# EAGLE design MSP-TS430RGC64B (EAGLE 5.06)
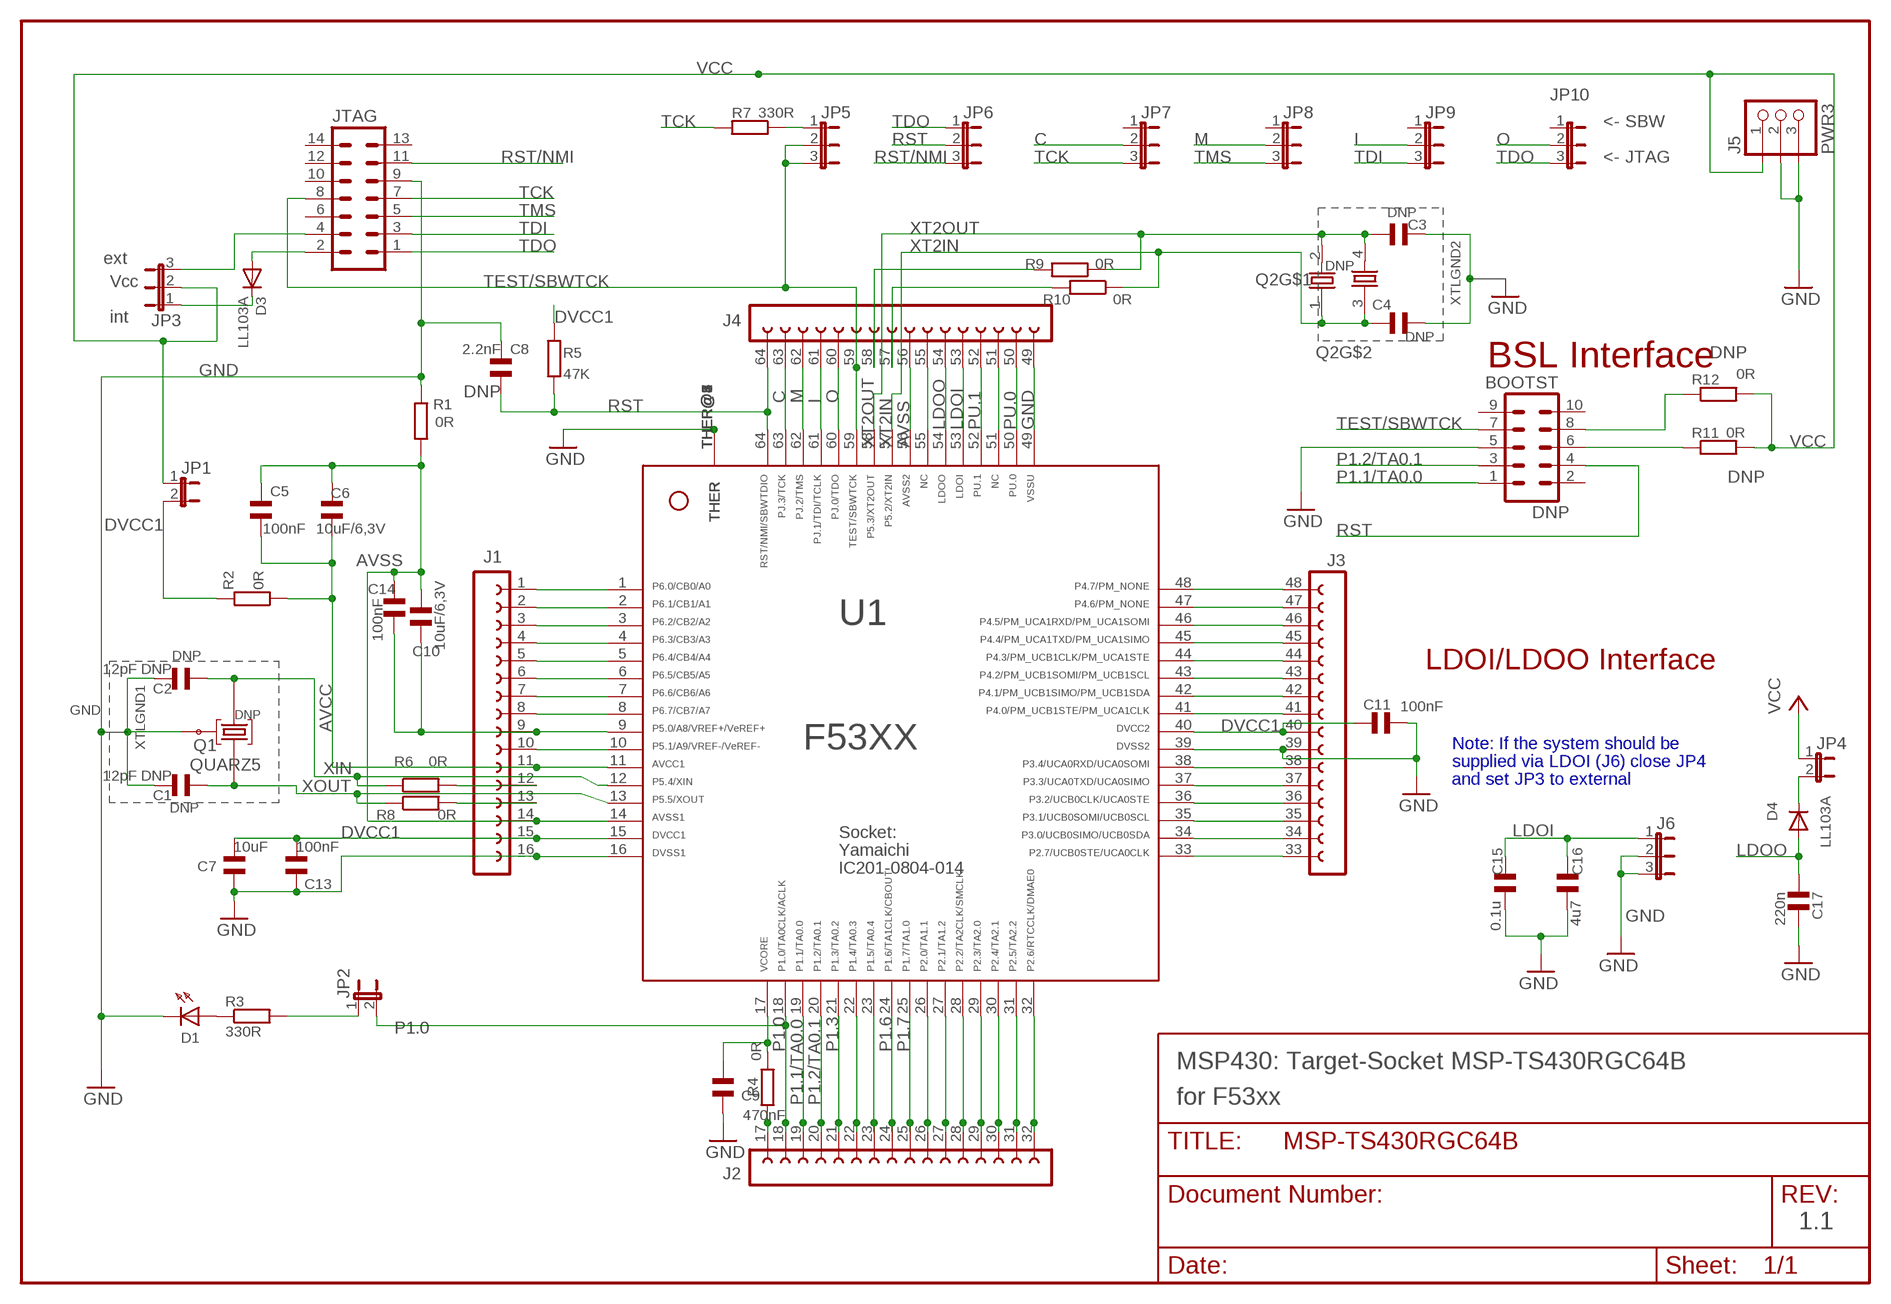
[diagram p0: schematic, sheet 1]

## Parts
BOOTST  ML10  [ML10]
C1  12pF DNP  CSMD0805  [CSMD0805]
C2  12pF DNP  CSMD0805  [CSMD0805]
C3  47pF  CSMD0805  [CSMD0805]
C4  47pF  CSMD0805  [CSMD0805]
C5  100nF  CSMD0805  [CSMD0805]
C6  10uF/6,3V  CSMD0805  [CSMD0805]
C7  10uF  CSMD0805  [CSMD0805]
C8  2.2nF  CSMD0805  [CSMD0805]
C9  470nF  CSMD0805  [CSMD0805]
C10  10uF/6,3V  CSMD0805  [CSMD0805]
C11  100nF  CSMD0805  [CSMD0805]
C13  100nF  CSMD0805  [CSMD0805]
C14  100nF  CSMD0805  [CSMD0805]
C15  0.1u  C_SMD0805  [0805]
C16  4u7  C_SMD0805  [0805]
C17  220n  C_SMD0805  [0805]
D1  LED30805  [DIODE_0805]
D3  LL103A  D  [SOD-80]
D4  LL103A  D  [SOD-80]
J1  FE16-1-1  [FE16-1-1]
J2  FE16-1-2  [FE16-1-2]
J3  FE16-1-3  [FE16-1-3]
J4  FE16-1-4  [FE16-1-4]
J5  PWR3  [PWR3]
J6  JP2ESMALLPAD  [JP2Z]
JP1  JP1E  [JP1]
JP2  JP1E  [JP1]
JP3  JP2ESMALLPAD  [JP2Z]
JP4  JP1E  [JP1]
JP5  JP2ESMALLPAD  [JP2Z]
JP6  JP2ESMALLPAD  [JP2Z]
JP7  JP2ESMALLPAD  [JP2Z]
JP8  JP2ESMALLPAD  [JP2Z]
JP9  JP2ESMALLPAD  [JP2Z]
JP10  JP2ESMALLPAD  [JP2Z]
JTAG  ML14  [ML14]
Q1  QUARZ5  [QUARZ5]
Q2  HCTC_XTL_4  [HCTC]
R1  0R  R_0805  [0805]
R2  0R  R_0805  [0805]
R3  330R  R_0805  [0805]
R4  0R  R_0805  [0805]
R5  47K  R_0805  [0805]
R6  0R  R_0805  [0805]
R7  330R  R_0805  [0805]
R8  0R  R_0805  [0805]
R9  0R  R_0805  [0805]
R10  0R  R_0805  [0805]
R11  0R  R_0805  [0805]
R12  0R  R_0805  [0805]
U1  F53XX---RGC64--S-PQFP-N64  [YAMAICHI-QFN11T064-006]

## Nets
51 [small]: J4.51 U1.51
56 [small]: J4.55 U1.55
AVCC [small]: C5.1 C6.2 J1.11 R2.1 U1.11
AVSS [small]: C5.2 C6.1 C10.2 C14.2 J1.14 J4.56 R1.2 U1.14 U1.56
C: J4.63 JP7.2 U1.63
DVCC1: C7.2 C11.1 C13.2 J1.15 J3.40 JP1.2 R2.2 R5.2 U1.15 U1.40
GND [small]: BOOTST.5 C7.1 C8.1 C9.1 C11.2 C13.1 C15.2 C16.2 C17.2 D1.K J1.16 J3.39 J4.49 J5.2 J5.3 J6.2 J6.3 JTAG.9 R1.1 U1.16 U1.39 U1.49 U1.THER@1(THER) U1.THER@2(THER) U1.THER@3(THER) U1.THER@4(THER) U1.THER@5(THER) U1.THER@6(THER) U1.THER@7(THER) U1.THER@8(THER)
I [small]: J4.61 JP9.2 U1.61
LDOI [small]: C15.1 C16.1 J4.53 J6.1 U1.53
LDOO [small]: C17.1 D4.1(A) J4.54 U1.54
M [small]: J4.62 JP8.2 U1.62
N$1: JP2.1 R3.2
N$3 [small]: C10.1 C14.1 J1.9 U1.9
N$4 [small]: J2.17 R4.1
N$5: J4.58 R9.2
N$6: J1.12 R6.2
N$7: D3.2(K) JP3.1
N$8: BOOTST.8 R12.1
N$9: J1.1 U1.1
N$10: J1.13 R8.2
N$11: J4.57 R10.2
N$12: J1.2 U1.2
N$13: J1.3 U1.3
N$14 [small]: J2.26 U1.26
N$15 [small]: J1.4 U1.4
N$16: BOOTST.6 R11.1
N$17 [small]: J2.23 U1.23
N$18: D1.A R3.1
N$19 [small]: J1.6 U1.6
N$20 [small]: J2.27 U1.27
N$21: J2.31 U1.31
N$22 [small]: J1.10 U1.10
N$23: JP3.3 JTAG.4
N$25: J3.33 U1.33
N$26 [small]: C9.2 R4.2 U1.17
N$27 [small]: J3.34 U1.34
N$28 [small]: J1.7 U1.7
N$29: J3.35 U1.35
N$30: D4.2(K) JP4.2
N$33 [small]: J3.36 U1.36
N$34: J2.28 U1.28
N$38: D3.1(A) JTAG.2
N$39 [small]: J3.37 U1.37
N$40: J3.38 U1.38
N$41: J3.41 U1.41
N$42 [small]: J3.42 U1.42
N$46: J2.22 U1.22
N$47 [small]: J3.43 U1.43
N$48: J3.44 U1.44
N$49 [small]: J3.45 U1.45
N$50 [small]: J3.46 U1.46
N$52: J3.47 U1.47
N$53: J3.48 U1.48
N$55 [small]: J2.29 U1.29
N$56 [small]: J2.30 U1.30
N$57: JP5.1 R7.1
N$58: J2.32 U1.32
N$99 [small]: J1.8 U1.8
N$102 [small]: J1.5 U1.5
O [small]: J4.60 JP10.2 U1.60
P1.0: J2.18 JP2.2 U1.18
P1.1/TA0.0: BOOTST.1 J2.19 U1.19
P1.2/TA0.1: BOOTST.3 J2.20 U1.20
P1.3 [small]: J2.21 U1.21
P1.6 [small]: J2.24 U1.24
P1.7: J2.25 U1.25
PU.0 [small]: J4.50 U1.50
PU.1 [small]: J4.52 U1.52
RST [small]: BOOTST.4 C8.2 J4.64 JP6.2 R5.1 U1.64
RST/NMI: JP6.3 JTAG.11
TCK: JP7.3 JTAG.7 R7.2
TDI: JP9.3 JTAG.3
TDO: JP6.1 JP10.3 JTAG.1
TEST/SBWTCK: BOOTST.7 J4.59 JP5.2 JP5.3 JTAG.8 U1.59
TMS: JP8.3 JTAG.5
VCC: J5.1 JP1.1 JP3.2 JP4.1 R11.2 R12.2
XIN: C2.1 Q1.1 R6.1 U1.12
XOUT [small]: C1.1 Q1.2 R8.1 U1.13
XT2IN [small]: C4.1 Q2.1 Q2.3 R10.1 U1.57
XT2OUT [small]: C3.1 Q2.2 Q2.4 R9.1 U1.58
XTLGND1: C1.2 C2.2 Q1.GND@0
XTLGND2: C3.2 C4.2
Unconnected: BOOTST.2 BOOTST.9 BOOTST.10 JP7.1 JP8.1 JP9.1 JP10.1 JTAG.6 JTAG.10 JTAG.12 JTAG.13 JTAG.14

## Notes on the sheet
- <- SBW
- <- JTAG
- DNP
- ext
- DNP
- Vcc
- int
- DNP
- DNP
- BSL Interface
- DNP
- DNP
- DNP
- DNP
- LDOI/LDOO Interface
- GND
- DNP
- Note: If the system should be
- supplied via LDOI (J6) close JP4
- and set JP3 to external
- DNP
- Socket:
- Yamaichi
- IC201-0804-014
- MSP430: Target-Socket MSP-TS430RGC64B
- for F53xx
- 1.1

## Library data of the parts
BOOTST = con-ml:ML10
C1-C11 C13 C14 = cap:CSMD0805
C15-C17 = ssmd:C_SMD
D1 = MSP430:LED3
D3 D4 = smd:D
J1 = CON-LSTA:FE16-1-1
J2 = CON-LSTA:FE16-1-2
J3 = CON-LSTA:FE16-1-3
J4 = CON-LSTA:FE16-1-4
J5 = MSP430:PWR3
J6 JP3 JP5-JP10 = jumper:JP2E: JUMPER
JP1 JP2 JP4 = jumper:JP1E: JUMPER
JTAG = con-ml:ML14: HARTING
Q1 = sMSP430:QUARZ5
Q2 = scrystal:HCTC_XTL_4
R1-R12 = smd:R_0805
U1 = TI_MSP430_v16_intern:F53XX---RGC64--S-PQFP-N64

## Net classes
0 default: width 0.254 mm, drill 0.305 mm
1 small: width 0.178 mm, drill 0.305 mm

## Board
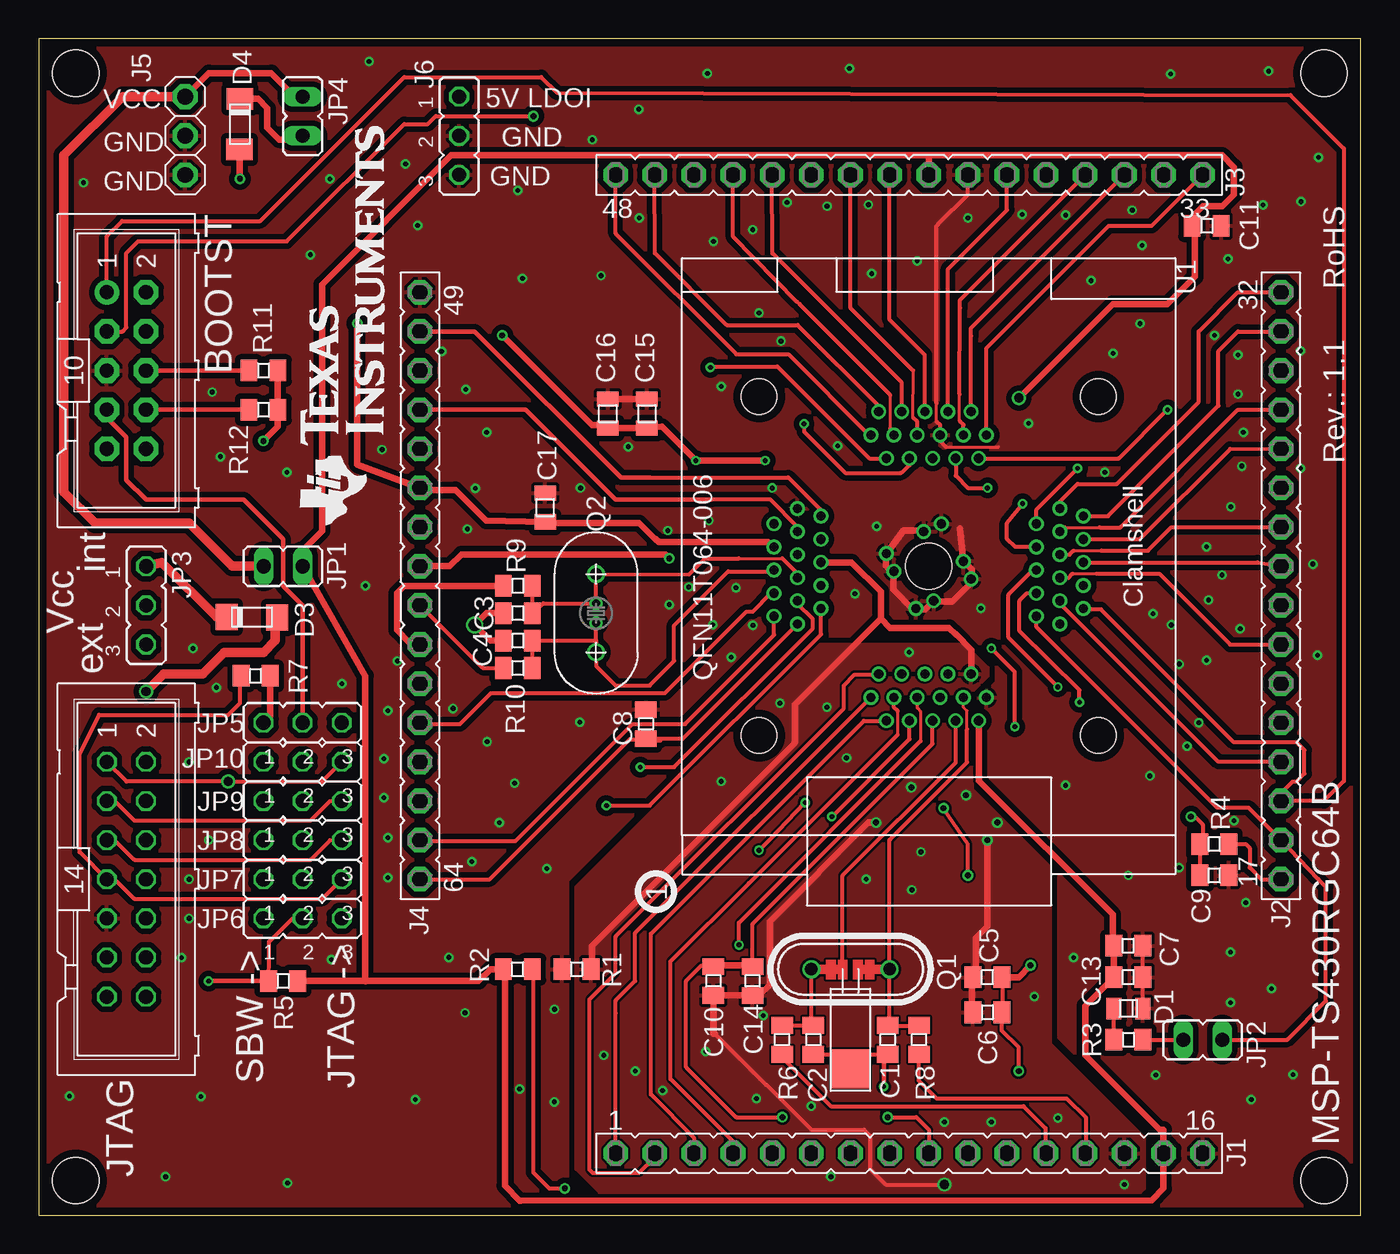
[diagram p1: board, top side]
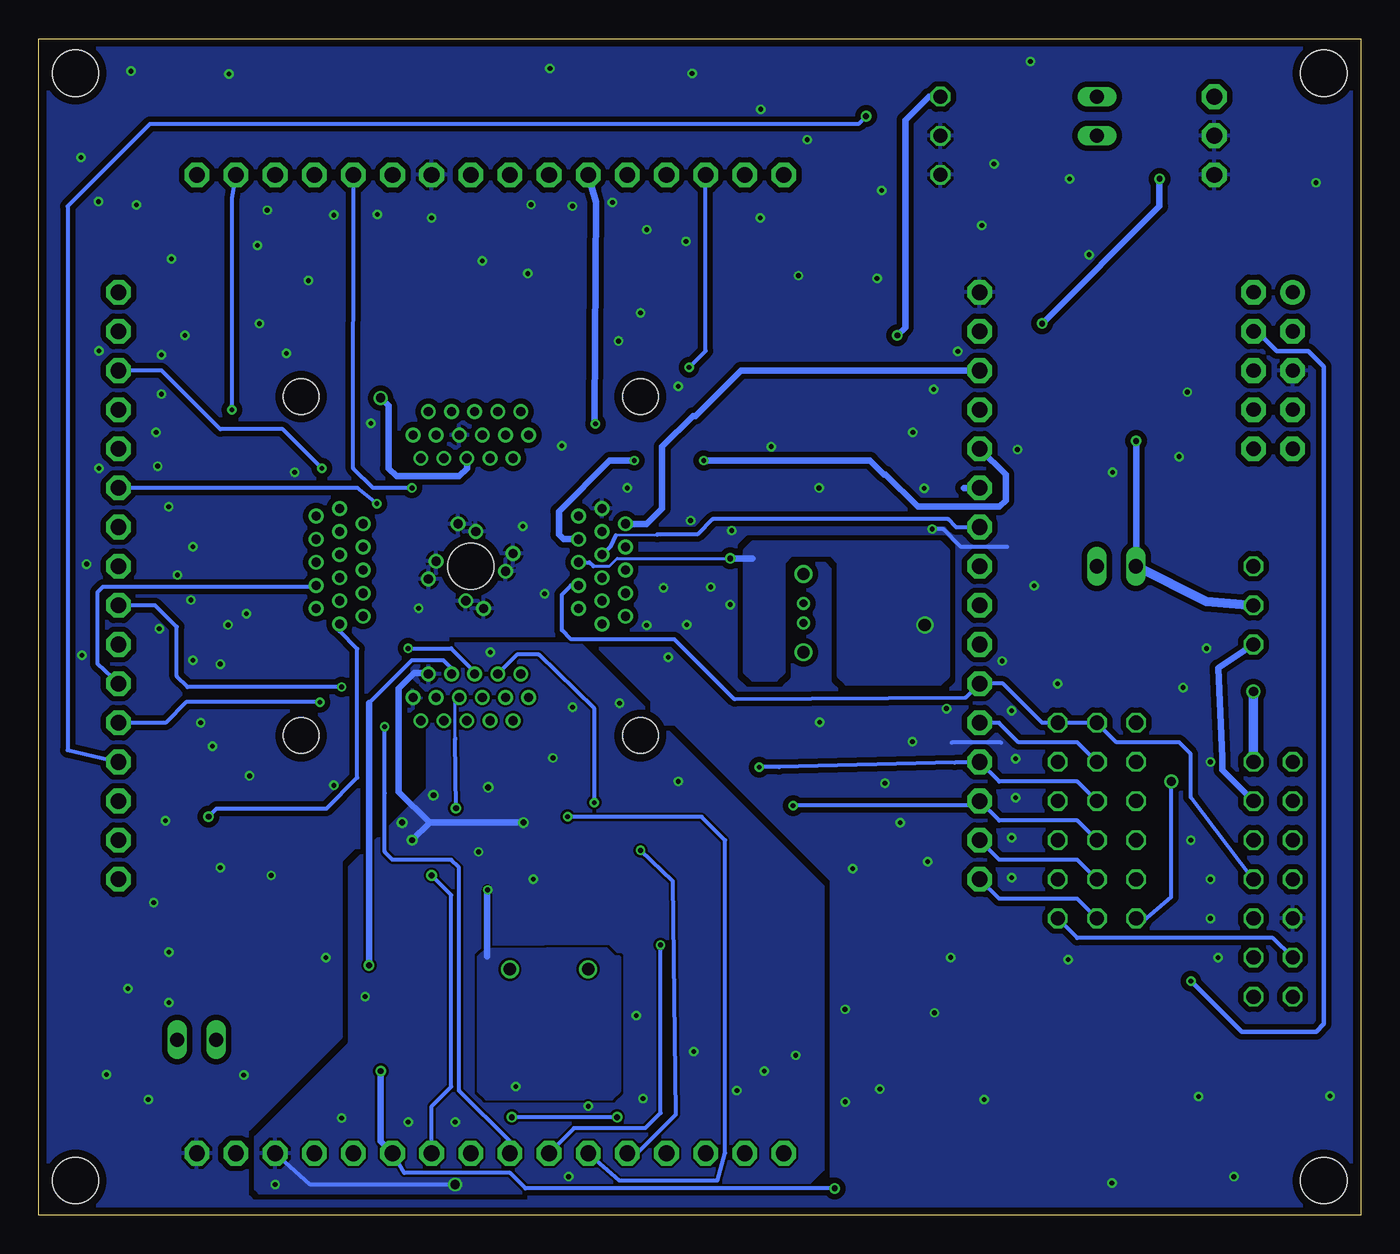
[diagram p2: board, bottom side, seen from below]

Size 85.83 x 76.38 mm. Coordinates in mm from the lower left corner, seen from the top.
Outline: 0,0 85.83,0 85.83,76.38 0,76.38 0,0
Copper layers (1*16): Top 0.035mm / dielectric 1.5mm / Bottom 0.035mm
Design rules "PCB-POOL *": minimum track width 6mil, minimum drill 0.3mm, track to track 6mil, track to pad 6mil, pad to pad 6mil, via to via 6mil, smd to smd 6mil, copper to edge 20mil, drill to drill 8mil, minimum pad ring 7mil, minimum via ring 6mil, stop-mask expansion 0mil, vias tented up to drill 25mil, thermal gap 8mil
Holes 3 mm at 2.41,74.13 83.43,74.13 83.43,2.25 2.41,2.25

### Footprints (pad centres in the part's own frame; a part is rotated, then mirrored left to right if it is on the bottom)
ML10 = drill 0.914 pad 1.6 round: 1 -5.08,-1.27 | drill 0.914 pad 1.6 octagon: 2 -5.08,1.27; 3 -2.54,-1.27; 4 -2.54,1.27; 5 0,-1.27; 6 0,1.27; 7 2.54,-1.27; 8 2.54,1.27; 9 5.08,-1.27; 10 5.08,1.27
CSMD0805 = smd 1.092 x 1.397: 1 -0.94,0; 2 0.94,0
0805 = smd 1 x 1.4: 1 -0.94,0; 2 0.94,0
DIODE_0805 = smd 1 x 1.4: A -0.94,0; K 0.94,0
SOD-80 = smd 1.397 x 1.702: 1 1.397,-0.025; 2 -1.88,0
FE16-1-1 = drill 1.016 pad 1.6 octagon: 1 -17.78,1.27; 2 -15.24,1.27; 3 -12.7,1.27; 4 -10.16,1.27; 5 -7.62,1.27; 6 -5.08,1.27; 7 -2.54,1.27; 8 0,1.27; 9 2.54,1.27; 10 5.08,1.27; 11 7.62,1.27; 12 10.16,1.27; 13 12.7,1.27; 14 15.24,1.27; 15 17.78,1.27; 16 20.32,1.27
FE16-1-2 = drill 1.016 pad 1.6 octagon: 17 -17.78,1.27; 18 -15.24,1.27; 19 -12.7,1.27; 20 -10.16,1.27; 21 -7.62,1.27; 22 -5.08,1.27; 23 -2.54,1.27; 24 0,1.27; 25 2.54,1.27; 26 5.08,1.27; 27 7.62,1.27; 28 10.16,1.27; 29 12.7,1.27; 30 15.24,1.27; 31 17.78,1.27; 32 20.32,1.27
FE16-1-3 = drill 1.016 pad 1.6 octagon: 33 -17.78,1.27; 34 -15.24,1.27; 35 -12.7,1.27; 36 -10.16,1.27; 37 -7.62,1.27; 38 -5.08,1.27; 39 -2.54,1.27; 40 0,1.27; 41 2.54,1.27; 42 5.08,1.27; 43 7.62,1.27; 44 10.16,1.27; 45 12.7,1.27; 46 15.24,1.27; 47 17.78,1.27; 48 20.32,1.27
FE16-1-4 = drill 1.016 pad 1.6 octagon: 49 -17.78,1.27; 50 -15.24,1.27; 51 -12.7,1.27; 52 -10.16,1.27; 53 -7.62,1.27; 54 -5.08,1.27; 55 -2.54,1.27; 56 0,1.27; 57 2.54,1.27; 58 5.08,1.27; 59 7.62,1.27; 60 10.16,1.27; 61 12.7,1.27; 62 15.24,1.27; 63 17.78,1.27; 64 20.32,1.27
PWR3 = drill 1.016 pad 1.6 octagon: 1 -2.54,0; 2 0,0; 3 2.54,0
JP2Z = drill 0.914 octagon: 1 -2.54,0; 2 0,0; 3 2.54,0
JP1 = drill 0.914 long: 1 0,-1.27; 2 0,1.27
ML14 = drill 0.914 octagon: 1 -7.62,-1.27; 2 -7.62,1.27; 3 -5.08,-1.27; 4 -5.08,1.27; 5 -2.54,-1.27; 6 -2.54,1.27; 7 0,-1.27; 8 0,1.27; 9 2.54,-1.27; 10 2.54,1.27; 11 5.08,-1.27; 12 5.08,1.27; 13 7.62,-1.27; 14 7.62,1.27
QUARZ5 = drill 0.813 round: 1 1.53,1.773; 2 1.52,-3.303 | smd 2.54 x 2.54: GND@0 -4.941,-0.762
HCTC = drill 0.5 round: 1 -0.635,0; 2 0.635,0 | drill 0.8 round: 3 -2.54,0; 4 2.54,0
0805' = smd 1.092 x 1.397: 1 -0.94,0; 2 0.94,0
YAMAICHI-QFN11T064-006 = drill 0.6 pad 0.9 round: 1 8.515,-3.75; 2 6.995,-3.25; 3 10.035,-2.75; 4 8.515,-2.25; 5 6.995,-1.75; 6 10.035,-1.25; 7 8.515,-0.75; 8 6.995,-0.25; 9 10.035,0.25; 10 8.515,0.75; 11 6.995,1.25; 12 10.035,1.75; 13 8.515,2.25; 14 6.995,2.75; 15 10.035,3.25; 16 8.515,3.75; 17 3.75,8.515; 18 3.25,6.995; 19 2.75,10.035; 20 2.25,8.515; 21 1.75,6.995; 22 1.25,10.035; 23 0.75,8.515; 24 0.25,6.995; 25 -0.25,10.035; 26 -0.75,8.515; 27 -1.25,6.995; 28 -1.75,10.035; 29 -2.25,8.515; 30 -2.75,6.995; 31 -3.25,10.035; 32 -3.75,8.515; 33 -8.515,3.75; 34 -6.995,3.25; 35 -10.035,2.75; 36 -8.515,2.25; 37 -6.995,1.75; 38 -10.035,1.25; 39 -8.515,0.75; 40 -6.995,0.25; 41 -10.035,-0.25; 42 -8.515,-0.75; 43 -6.995,-1.25; 44 -10.035,-1.75; 45 -8.515,-2.25; 46 -6.995,-2.75; 47 -10.035,-3.25; 48 -8.515,-3.75; 49 -3.75,-8.515; 50 -3.25,-6.995; 51 -2.75,-10.035; 52 -2.25,-8.515; 53 -1.75,-6.995; 54 -1.25,-10.035; 55 -0.75,-8.515; 56 -0.25,-6.995; 57 0.25,-10.035; 58 0.75,-8.515; 59 1.25,-6.995; 60 1.75,-10.035; 61 2.25,-8.515; 62 2.75,-6.995; 63 3.25,-10.035; 64 3.75,-8.515; THER@1 -0.325,2.25; THER@2 0.825,2.75; THER@3 2.25,0.325; THER@4 2.75,-0.825; THER@5 0.325,-2.25; THER@6 -0.825,-2.75; THER@7 -2.25,-0.325; THER@8 -2.75,0.825 | hole 2.3: -11,-11; -11,11; 11,-11; 11,11 | hole 3: 0,0

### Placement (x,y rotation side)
BOOTST  5.71,54.83 270 top
C1  55.11,11.39 270 top
C2  50.29,11.39 270 top
C3  31.11,39.08 180 top
C4  31.11,37.3 180 top
C5  61.59,15.46 180 top
C6  61.59,13.17 0 top
C7  70.73,17.49 180 top
C8  39.42,31.88 270 top
C9  76.32,22.06 180 top
C10  43.81,15.2 270 top
C11  75.81,64.22 0 top
C13  70.73,15.46 180 top
C14  46.35,15.2 270 top
C15  39.49,52.03 90 top
C16  36.95,52.03 90 top
C17  32.88,45.94 90 top
D1  70.73,13.42 0 top
D3  14.09,38.82 0 top
D4  13.07,70.58 270 top
J1  55.24,2.76 0 top
J2  81.91,39.59 90 top
J3  57.78,68.8 180 top
J4  23.49,42.13 270 top
J5  9.52,70.07 270 top
J6  27.3,70.07 270 top
JP1  15.87,42.13 270 top
JP2  75.56,11.39 270 top
JP3  6.98,39.59 270 top
JP4  17.14,71.34 180 top
JP5  17.14,31.97 0 top
JP6  17.14,19.27 0 top
JP7  17.14,21.81 0 top
JP8  17.14,24.35 0 top
JP9  17.14,26.89 0 top
JP10  17.14,29.43 0 top
JTAG  5.71,21.81 270 top
Q1  51.93,14.44 90 top
Q2  36.19,39.08 90 top
R1  0R  [0805']  34.92,15.97 0 top
R2  0R  [0805']  31.11,15.97 180 top
R3  330R  [0805']  70.73,11.39 0 top
R4  0R  [0805']  76.32,24.09 180 top
R5  47K  [0805']  15.87,15.2 0 top
R6  0R  [0805']  48.25,11.39 270 top
R7  330R  [0805']  14.09,35.01 180 top
R8  0R  [0805']  57.14,11.39 270 top
R9  0R  [0805']  31.11,40.86 180 top
R10  0R  [0805']  31.11,35.52 180 top
R11  0R  [0805']  14.6,54.83 0 top
R12  0R  [0805']  14.6,52.29 0 top
U1  57.78,42.13 270 top
U$1  [LOGO2008_TPLACE]  20.11,54.84 90 top

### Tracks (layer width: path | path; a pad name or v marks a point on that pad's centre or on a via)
51
  Bottom 0.406: U1.51 46.37,44.88 45.36,45.89 45.36,49.89 43.36,51.89 43.19,51.89 40.25,54.83 J4.51
56
  Bottom 0.2: 45.69,44.16 48.38,44.13
  Bottom 0.254: J4.55 26.28,44.67 26.79,45.17 42.08,45.17 43.07,44.18 45.66,44.18 45.69,44.16 | U1.55 48.7,43.41 48.38,44.13
AVCC  (via drill 0.38)
  Top 0.254: v34.15,1.74 33.14,1.74 32.12,2.76 32.12,15.89 R2.1 | 62.6,15.38 62.6,13.25 C6.2 62.53,11.98 63.62,10.89 v63.62,9.36
  Top 0.406: 62.6,15.38 C5.1 63.62,15.46 v64.38,16.22 | v63.62,9.36 63.57,9.41
  Bottom 0.254: U1.11 59.03,35.03 59.05,35.01 59.05,35.52 59.56,36.03 61.59,36.03 64.38,33.24 | J1.11 62.1,2.76 55.24,2.76 54.22,1.74 v34.16,1.74 v34.15,1.74
  Bottom 0.406: 64.38,33.24 64.38,16.98 v64.38,16.22 | v63.62,9.36 63.62,4.79 J1.11
AVSS  (via drill 0.3, 0.38, 0.6)
  Top 0.254: v58.8,1.99 54.99,1.99 53.97,3.01 53.97,5.17 53.58,5.55 50.16,5.55 47.23,8.47 47.21,8.47 43.9,11.79 | v40.94,42.64 40.96,42.64
  Top 0.406: 45.92,14.26 C14.2 46.78,14.26 | 46.78,14.26 47.46,14.95 47.46,19.09 53.86,25.49 v54.36,25.49 | U1.14 60.56,35.16 60.56,36.69 59.56,37.69 59.54,37.69 59.1,38.13 55.26,38.13 54.66,38.73 | 54.66,38.73 54.66,40.49 52.77,42.38 U1.56 | 60.57,12.92 60.57,14.95 60.65,14.95 C5.2 60.82,15.63 60.82,18 61.59,18.76 v61.59,24.35 | 54.66,38.73 49.1,33.16 49.1,30.69 49.06,30.69 49.06,30.62 35.93,17.49 35.93,16.04 R1.2 35.68,15.76 | v40.94,42.64 40.68,42.89 27.45,42.89 26.68,42.13 25,42.13 J4.56 | 46.78,14.26 C10.2 43.81,11.79 43.9,11.79
  Bottom 0.2: 49.83,42.13 48.78,42.13 48.28,42.64 v40.94,42.64
  Bottom 0.254: v58.8,1.99 68.19,1.99 J1.14 | U1.56 50.08,42.38 49.83,42.13
  Bottom 0.406: 60.46,25.49 v54.36,25.49 | 60.46,25.49 62.46,27.49 62.46,34.19 61.46,35.19 60.59,35.19 U1.14 | 60.46,25.49 60.46,25.47 v61.59,24.35
  other vias: 44.31,28.16 48.12,33.24 51.17,32.98 52.44,29.68 53.71,21.81 57.27,23.59 36.69,10.38 38.73,9.36 40.5,8.09 43.3,10.63 56.68,21.12 50.16,7.08 51.43,2.5 56.65,27.77 60.2,27.26 62.23,25.49 58.79,6.06 61.84,6.06 66.16,6.31 64.63,14.19 70.48,2 56.51,36.54 47.03,12.97 46.6,7.58
  pour Top: 61.59,35.52 61.59,35.02 60.57,34 60.57,27.65 65.65,22.57 65.65,11.14 71.75,5.04 71.75,1.74 71.49,1.49 36.44,1.49 34.92,3.01 34.92,21.3 50.66,37.05 60.06,37.05
  pour Bottom (rank 2): 61.59,35.52 61.59,35.02 60.57,34 60.57,27.65 65.65,22.57 65.65,11.14 71.75,5.04 71.75,1.74 71.49,1.49 36.44,1.49 34.92,3.01 34.92,21.3 50.66,37.05 60.06,37.05
C
  Top 0.254: U1.63 47.74,37.67 41.96,31.89 38.56,31.89 30.96,24.29 24.82,24.29 J4.63
  Bottom 0.254: JP7.2 18.41,23.08 23.48,23.08 J4.63
DVCC1  (via drill 0.6)
  Top 0.254: C11.1 75.05,64.05
  Top 0.406: R5.2 21.2,15.2 | 21.2,15.2 21.2,35.01 JP1.2 17.14,43.15 18.41,44.41 18.41,60.42 26.79,68.8 34.15,68.8 | U1.15 61.03,28.46 61.03,28.21 69.71,19.52 69.71,17.57 C7.2 | v63.62,53.05 69.72,59.14 73.27,59.14 75.05,60.92 75.05,64.05 | 34.15,68.8 33.65,68.8 | 34.15,68.8 57.78,68.8 | 57.78,68.8 76.83,68.8 77.59,68.03 77.59,66.26 76.83,65.5 75.56,65.5 74.87,64.81 C11.1 | 57.78,68.8 J3.40 | C7.2 C13.2 67.94,13.6 67.94,10.38 72.76,5.55 73.02,5.55 J1.15 73.02,1.74 72.26,0.98 31.29,0.95 31.23,0.95 30.27,1.92 30.27,15.86 R2.2 29.33,15.97 28.57,15.2 21.23,15.2 21.22,15.19 21.2,15.2 | C7.2 69.46,17.49
  Bottom 0.406: U1.40 58.03,48.48 58.54,47.97 62.61,47.97 63.11,48.48 63.11,52.54 v63.62,53.05
GND  (via drill 0.3)
  Top 0.2: 58.29,51.52 58.29,52.68 58.29,52.69
  Top 0.203: 58.89,49.87 62.32,49.87
  Top 0.254: U1.39 58.53,51.28 58.29,51.52 | 58.29,52.69 58.29,64.23 | C7.1 C13.1 D1.K | 58.54,50.76 58.54,50.26 58.89,49.87 | 58.38,64.32 60.32,66.26 J3.39
  Top 0.406: 57.41,44.46 56.14,44.46 54.99,42.89 54.99,42.13 55.49,41.62 55.49,40.6 56.76,39.33 57.53,39.33 58.03,39.84 59.3,39.84 60.57,41.11 60.57,41.91 U1.THER@1 59.78,44.57 | C16.2 C15.2
  Bottom 0.254: v27.83,44.54 27.11,44.54 25.96,43.39 22.99,43.39 22.98,43.4 | 23.36,30.69 26.56,30.69
  other vias: 40.94,39.64 21.46,74.89 83.07,68.67 79.48,65.58 79.83,74.26 52.64,74.43 43.41,74.11 38.95,71.78 35.94,69.81 46.35,63.97 43.81,63.21 61.17,39.4 69.74,55.94 54.4,44.72 48.19,56.74 8.25,2.5 2.01,7.74 10.54,7.71 9.27,16.73 9.77,21.81 11.04,24.35 9.77,29.43 10.03,36.79 19.68,34.51 21.2,40.86 22.3,49.7 17.65,62.34 11.81,49.24 2.92,67.02 30.9,28.04 29.92,25.48 38.98,64.73 29.09,50.82 31.23,8.2 26.64,16.73 33.48,7.36 80.03,14.72 77.99,38.08 77.85,53.3 33.49,13.36 77.36,17.08 77.59,25.62 75.31,31.97 81.43,9.13 82.71,42.27 77.38,45.98 71.62,62.95 60.32,64.73 66.67,64.92 81.91,48.48 75.81,43.4 27.74,53.61 31.11,66.51 46.76,58.57 23.29,35.98 22.67,32.74 22.41,27.09 22.67,24.51 36.51,60.99 72.13,28.52 78.35,20.28 28.35,47.19 35.12,32 74.04,22.57 66.67,27.9 63.83,64.96 69.21,48.22 71.5,57.87 68.32,60.67 73.48,74.08 76.32,57.11 72.34,39.03 78.2,50.82 32.99,22.49 24.45,7.51 16.16,2.09 27.68,13.14 22.67,21.92 35.17,47.21 47.62,47.21 18.92,67.27 23.82,68.24 16.12,48.22 24.61,64.25 42.21,40.78 40.85,44.45 52.99,40.35 78.71,7.51 67.18,16.73 81.93,65.79 81.91,56.1 72.51,9.11 9.77,19.27 11.55,34.25 76.81,41.56 74.54,30.44 48.58,65.75 51.18,65.49 53.86,65.59 54.08,61.12 57.02,61.94 70.99,65.24 74.04,35.78 75.81,36.03 73.53,38.32 77.85,55.84 26.9,32.89 29.12,30.74 77.36,13.8 64.26,51.4 75.94,39.93 78.1,48.62 83,36.35 31.41,60.81 26.17,56.08 43.51,45.09 51.88,49.95 44.32,53.81 44.97,36.22 28.12,22.94 19.02,16.6 45.27,40.72 43.77,38.32 70.73,22.06 46.36,38.3 11.27,53.43 77.21,62.07 22.41,29.63 38.27,49.89
  pour Bottom (isolate 0.356, rank 3): 0.25,76.16 85.59,76.16 85.59,0.34 0.25,0.22
  pour Top (isolate 0.356, rank 2): 0.25,76.16 85.59,76.16 85.59,0.34 0.25,0.22
I  (via drill 0.3)
  Top 0.254: U1.61 49.27,39.68 50.26,38.69 50.26,38.09 41.26,29.09 v39.06,29.09
  Bottom 0.254: JP9.2 18.41,28.16 23.48,28.16 J4.61 24.8,29.39 26.36,29.39 37.76,29.09 v39.06,29.09
LDOI  (via drill 0.3, 0.38)
  Top 0.406: v47.16,48.99 v42.66,48.99 40.46,51.18 C15.1 C16.1 36.86,51.27 35.93,51.27 v30.09,57.11
  Bottom 0.406: J4.53 24.72,49.75 23.06,48.09 23.06,46.39 23.46,45.99 28.76,45.99 30.86,48.09 30.96,48.09 31.86,48.99 v42.66,48.99 | U1.53 51.76,43.89 52.06,44.19 52.06,45.69 48.76,48.99 v47.16,48.99 | J6.1 28.06,72.61 29.58,71.08 29.58,57.62 v30.09,57.11
LDOO  (via drill 0.38)
  Top 0.254: U1.54 47.67,43.38 47.36,43.69
  Top 0.406: 47.36,43.69 40.26,43.69 40.06,43.89 40.02,43.89 38.98,44.92 33.05,44.92 C17.1 29.06,45.09 27.06,47.09 25.38,47.09 25.26,47.21 J4.54 20.69,48.73 v20.69,57.88 | D4.1 13.05,67.3 v13.07,67.27
  Bottom 0.406: J4.54 25.78,47.21 | v13.07,67.27 13.07,65.5 v20.69,57.88
M  (via drill 0.3)
  Top 0.254: U1.62 50.78,37.71 39.66,26.59 v36.86,26.59
  Bottom 0.254: JP8.2 18.41,25.62 23.48,25.62 J4.62 25.06,26.59 v36.86,26.59
N$1
  Top 0.254: R3.2 JP2.1
N$3  (via drill 0.38)
  Top 0.254: U1.9 58.03,30.59 46.35,18.91 C14.1 | v48.28,6.37 45.28,6.37 42.03,9.61 42.03,15.21 43.04,16.22 43.73,16.22 C10.1 | v55.11,6.37 56.96,6.37 57.78,5.55 J1.9
  Top 0.406: C14.1 46.6,16.22 43.81,16.22 C10.1
  Bottom 0.254: v48.28,6.37 v55.11,6.37
N$4
  Top 0.254: R4.1 78.35,24.09 78.6,23.84 78.6,22.57 79.37,21.81 J2.17
N$5
  Top 0.406: R9.2 23.73,40.86 23.26,40.39 23.26,37.99 24.06,37.19 24.62,37.19 J4.58
N$6
  Top 0.254: J1.12 65.36,4.07 65.36,5.65 63.93,7.07 51.43,7.07 48.5,10 48.5,10.45 R6.2
N$7
  Top 0.406: 11.55,38.82 D3.2
  Top 0.61: 11.55,38.82 8,42.38 JP3.1
N$8
  Top 0.305: BOOTST.8 R12.1 | R12.1 13.83,52.29 14.09,52.03 13.91,52.03 R12.1
N$9
  Top 0.254: J1.1 37.46,13.12 37.46,13.94 38.73,15.2 38.73,18.31 U1.1
N$10
  Top 0.254: J1.13 67.96,4.05 67.96,6.35 66.72,7.58 58.29,7.58 57.14,8.73 R8.2
N$11
  Top 0.254: R10.2 28.82,35.52 J4.57
N$12
  Top 0.254: J1.2 40,3.77 38.97,2.75 35.96,2.75 35.75,2.96 35.75,14.01 37.46,15.71 37.46,18.09 52.26,32.9 52.26,34.39 52.96,35.09 54.49,35.09 U1.2
N$13
  Top 0.254: J1.3 42.54,5.04 39.75,7.84 39.75,18.28 53.56,32.09 U1.3
N$14
  Top 0.2: 67.18,43.14 69.01,43.14
  Top 0.254: J2.26 73.53,44.67 72,43.14 69.01,43.14 68.98,43.14 | U1.26 66.91,42.88 67.18,43.14
N$15
  Top 0.2: 55.77,31.2 55.77,32.73
  Top 0.254: U1.4 55.53,32.95 55.77,32.73 | 55.77,31.2 46.1,21.55 41.02,16.47 41.02,8.85 45.08,4.79 J1.4
N$16
  Top 0.305: BOOTST.6 R11.1
N$17
  Top 0.2: 67.1,41.64 68.68,41.64
  Top 0.254: J2.23 77.34,37.05 72.74,41.64 68.68,41.64 | U1.23 66.83,41.38 67.1,41.64
N$18
  Top 0.254: R3.1 D1.A
N$19  (via drill 0.3)
  Top 0.254: U1.6 56.53,30.91 v51.49,25.87
  Bottom 0.254: v51.49,25.87 42.79,25.87 41.27,24.35 41.27,4.03 41.78,2.25 48.13,2.25 J1.6
N$20  (via drill 0.3)
  Top 0.254: U1.27 63.39,43.38 62.86,43.9 62.86,44.92 v63.88,46.19
  Bottom 0.254: v63.88,46.19 65.15,47.21 J2.27
N$21
  Top 0.254: U1.31 69.41,45.38 76.58,52.54 76.58,56.1 77.85,57.37 J2.31
N$22  (via drill 0.38)
  Top 0.254: v60.32,22.06 60.32,24.09 v58.74,26.42
  Bottom 0.2: 58.79,30.95 58.79,33.34 U1.10
  Bottom 0.254: J1.10 60.32,7.07 59.05,8.34 59.05,20.79 v60.32,22.06 | v58.74,26.42 58.79,30.9 58.79,30.95
N$23
  Bottom 0.406: JTAG.4 9.01,28.92 9.01,29.68 9.27,35.52 JP3.3
N$25
  Top 0.254: U1.33 61.53,56.29 61.53,56.3 69.46,64.23 72.25,64.23 J3.33
N$26  (via drill 0.38)
  Top 0.254: v74.79,25.87 75.05,25.87 75.56,25.36 75.56,24.27 R4.2 C9.2
  Bottom 0.254: U1.17 66.3,37.91 65.15,36.76 65.15,28.41 67.17,26.38 74.29,26.38 v74.79,25.87
N$27  (via drill 0.3)
  Top 0.254: U1.34 70.11,49.12 v73.27,52.29
  Bottom 0.254: v73.27,52.29 73.27,66 J3.34
N$28  (via drill 0.3)
  Top 0.2: U1.7 57.03,32.92 57.27,32.68 57.27,30.78
  Top 0.254: 57.27,30.78 57.25,30.78 45.46,18.99 v45.46,17.55
  Bottom 0.254: v45.46,17.55 45.46,6.65 46.46,5.65 51.08,5.65 J1.7
N$29
  Top 0.254: U1.35 60.53,57.07 60.53,57.58 J3.35
N$30
  Top 0.406: D4.2 14.24,72.46 14.85,71.85 14.85,70.58 15.61,69.81 16.88,69.81 JP4.2
N$33
  Top 0.2: 59.81,51.52 59.78,51.57 59.78,53.29
  Top 0.254: U1.36 60.03,51.31 59.81,51.52 | 59.78,53.29 59.81,58.89 59.81,59.4 J3.36
N$34
  Top 0.254: U1.28 71.47,43.88 77.34,49.75 J2.28
N$38  (via drill 0.6)
  Top 0.61: v6.98,34 8.12,35.14 10.66,35.14 12.06,36.54 14.6,36.54 15.36,37.3 15.36,38.67 D3.1
  Bottom 0.61: JTAG.2 v6.98,34
N$39  (via drill 0.3)
  Top 0.254: U1.37 59.53,48 60.32,47.21 v61.59,47.21
  Bottom 0.254: v61.59,47.21 64.13,47.21 65.4,48.48 J3.37
N$40
  Top 0.254: U1.38 59.03,61.41 62.86,65.24 J3.38
N$41
  Top 0.254: U1.41 57.53,55.84 55.24,58.13 J3.41
N$42
  Top 0.2: 56.76,51.77 56.77,54.8 56.76,54.83
  Top 0.254: U1.42 57.03,51.51 56.76,51.77 | 56.76,54.83 52.7,58.89 J3.42
N$46
  Bottom 0.254: J2.22 82.01,35.81 82.01,40.44 81.66,40.79 67.91,40.79 U1.22 67.94,40.86
N$47  (via drill 0.3)
  Top 0.254: U1.43 56.53,48.69 56.1,48.26 55.96,48.19 52.36,48.19 49.68,50.86 v49.68,51.36
  Bottom 0.406: J3.43 49.65,65.75 49.75,51.92 49.75,51.43 v49.68,51.36
N$48
  Top 0.254: U1.44 56.03,54.04 47.62,62.45 J3.44
N$49
  Top 0.2: 55.28,51.08 55.29,53.22
  Top 0.254: U1.45 55.53,50.73 55.28,51.08 | 55.29,53.22 49.4,59.14 49.24,59.28 45.08,63.52 J3.45
N$50  (via drill 0.3)
  Top 0.254: U1.46 53.92,49.12 47.96,55.09 43.67,55.09 v43.61,55.03
  Bottom 0.254: v43.61,55.03 42.54,56.1 J3.46
N$52
  Top 0.254: J3.47 40,62.45 44.66,57.79 49.26,57.79 54.53,52.52 U1.47
N$53
  Top 0.254: J3.48 37.46,63.72 45.29,55.89 48.66,55.89 53.91,50.64 U1.48
N$55
  Top 0.2: 66.59,44.64 68.88,44.64
  Top 0.254: U1.29 66.38,44.38 66.59,44.64 | 68.88,44.64 70.2,44.64 77.85,52.29 J2.29
N$56  (via drill 0.3)
  Top 0.254: U1.30 64.78,45.82 v67.43,48.48
  Bottom 0.254: v67.43,48.48 69.97,51.02 74.04,51.02 77.85,54.83 J2.30
N$57
  Top 0.406: R7.1 15.03,32.4 JP5.1
N$58
  Top 0.254: U1.32 66.3,46.32 67.43,47.46 69.97,47.46 75.31,52.79 75.31,57.37 77.85,59.91 J2.32
N$99  (via drill 0.3)
  Top 0.254: v61.84,36.79 63.37,35.27 v63.37,31.71
  Bottom 0.254: U1.8 57.53,35.27 59.05,36.79 v61.84,36.79 | v63.37,31.71 63.37,27.39 63.36,27.39 63.36,23.59 62.86,23.08 59.05,23.08 58.54,22.57 58.54,8.09 55.24,4.79 J1.8
N$102  (via drill 0.3)
  Top 0.254: v46.76,23.69 47.46,24.39 v49.76,26.79
  Bottom 0.254: J1.5 46.98,4.03 44.46,6.55 44.66,21.69 v46.76,23.69 | v49.76,26.79 49.76,32.89 53.36,36.39 54.78,36.39 U1.5
O
  Top 0.254: U1.60 47.55,40.38 46.36,39.19 45.96,39.19 40.66,33.89 29.36,33.89 27.36,31.89 24.84,31.89 J4.60
  Bottom 0.254: JP10.2 18.41,30.7 22.22,30.7 23.49,31.97 J4.60
P1.0
  Top 0.254: U1.18 64.78,38.18 76.51,26.45 78.54,26.45 J2.18 83.07,21.81 83.56,21.32 83.56,13.91 81.04,11.39 JP2.2
P1.1/TA0.0
  Top 0.254: U1.19 67.86,39.33 68.96,39.33 77.59,30.7 81.66,30.7 82.16,30.19 82.16,28.67 81.65,28.16 81.4,28.16 80.64,27.4 J2.19 83.43,26.89 84.72,28.18 84.72,69.23 81.25,72.71 33.65,72.86 32.63,73.88 23.74,73.88 14.39,64.53 5.43,64.53 4.44,63.54 BOOTST.1
P1.2/TA0.1  (via drill 0.38)
  Top 0.254: U1.20 66.3,39.71 76.58,29.43 J2.20 | BOOTST.3 5.45,57.37 5.71,57.62 5.71,62.45 6.47,63.21 16.12,63.21 23.74,70.83 25.26,70.83 25.77,71.34 v32.12,71.34
  Bottom 0.254: v32.12,71.34 32.63,70.83 78.6,70.83 83.94,65.5 83.94,30.19 J2.20
P1.3  (via drill 0.3)
  Top 0.254: U1.21 64.16,40.38 63.67,39.89 63.67,37.91 67.56,34.09 67.57,34.08 v67.57,33.31 67.57,33.3
  Bottom 0.254: v67.57,33.31 76.25,33.31 77.59,31.97 J2.21
P1.6  (via drill 0.3)
  Top 0.254: U1.24 64.55,41.88 62.96,40.29 62.96,37.49 v66.16,34.29
  Bottom 0.254: v66.16,34.29 76.16,34.29 76.86,34.99 76.86,38.19 78.26,39.59 J2.24
P1.7
  Top 0.254: U1.25 79.12,42.38 J2.25
PU.0
  Top 0.254: U1.50 50.78,45.76 48.66,47.89 39.66,47.89
  Top 0.305: 39.66,47.89 37.79,47.89 28.31,57.37 J4.50
PU.1
  Top 0.254: U1.52 49.27,44.68 47.46,46.49 43.69,46.49 43.65,46.44
  Top 0.305: 43.65,46.44 37.46,46.44 31.61,52.29 J4.52
RST  (via drill 0.3)
  Top 0.254: JP6.2 16.48,19.27 14.96,17.75 14.96,16.76 R5.1 | J4.64 29.28,21.81 38.36,30.89 40.26,30.89 40.36,30.79 39.57,30.79 C8.2 41.83,30.94 U1.64
  Top 0.305: v11.04,15.2 R5.1
  Bottom 0.254: JP6.2 18.41,20.54 23.48,20.54 J4.64
  Bottom 0.305: BOOTST.4 6.72,57.37 5.45,56.1 3.42,56.1 2.4,55.08 2.4,12.41 2.91,11.9 7.74,11.9 v11.04,15.2
RST/NMI
  Bottom 0.254: JTAG.11 5.71,18 18.41,18 JP6.3
TCK
  Top 0.254: JP7.3 18.41,20.54 6.22,20.54 4.95,21.81 JTAG.7 2.66,23.58 2.66,29.93 3.93,32.47 12.31,32.47 13.08,33.24 13.08,34.94 R7.2
TDI
  Top 0.254: JTAG.3 4.95,26.89 6.22,25.62 17.65,25.62 18.92,26.89 JP9.3
TDO  (via drill 0.6)
  Top 0.254: JTAG.1 5.71,28.16 v12.31,28.16 18.41,28.16 JP10.3
  Bottom 0.254: JP6.1 14.09,19.14 12.31,20.66 v12.31,28.16
TEST/SBWTCK
  Top 0.305: BOOTST.7 4.44,51.78 5.71,50.51 5.71,47.72 6.98,46.45 13.33,46.45 15.87,43.91 15.87,40.86 17.14,39.59 JP5.2
  Bottom 0.254: JTAG.8 11.04,27.14 11.04,29.93 11.81,30.7 15.87,30.7 JP5.2 JP5.3 20.69,31.97 23.23,34.51 J4.59 25.68,33.59 40.66,33.49 44.56,37.39 51.26,37.39 51.86,37.99 51.86,40.29 51.27,40.88 U1.59
TMS
  Top 0.254: JTAG.5 4.95,24.35 6.22,23.08 17.65,23.08 18.92,24.35 JP8.3
VCC  (via drill 0.38)
  Top 0.406: R11.2 R12.2 15.54,51.2 v14.6,50.26 | JP4.1 16.63,72.61 15.1,74.13 11.05,74.13 J5.1
  Top 0.61: JP1.1 12.57,42.13 9.77,44.92 3.67,44.92 1.64,46.95 1.64,68.8 5.45,72.61 J5.1
  Bottom 0.305: JP1.1
  Bottom 0.406: JP1.1 v14.6,50.26
  Bottom 0.61: JP3.2 10.03,39.84 JP1.1
XIN
  Top 0.254: U1.12 59.53,29.39 52.19,22.05 52.19,15.84 50.16,15.84 | 50.16,15.84 Q1.1 | 50.16,15.84 50.16,12.71 C2.1 R6.1
XOUT
  Top 0.2: U1.13 60.03,32.97 60.27,32.74 60.27,31.54
  Top 0.254: 60.27,31.54 60.27,29.4 55.26,24.39 55.24,24.39 55.24,16.09 55.24,12.71 | C1.1 55.24,12.71 | 55.24,12.71 55.24,12.28 56.59,12.28 R8.1
  Top 0.406: Q1.2 55.24,16.09
XT2IN
  Top 0.254: 32.13,37.3 C4.1 | R10.1 32.05,37.22 32.13,37.3 | U1.57 47.66,41.79 44.76,41.79 41.26,38.29 41.26,35.99 39.66,34.39 37.46,34.39 36.19,35.66 36.19,36.62 | 32.13,37.3 36.18,37.3 36.19,37.3 | 36.19,37.3 Q2.1 | 36.19,37.3 Q2.3
  Top 0.305: Q2.3 36.19,36.62
XT2OUT
  Top 0.2: 45.46,42.63 48.28,42.63
  Top 0.254: 32.13,39.08 32.76,39.71 Q2.2 Q2.4 42.23,41.59 43.27,42.63 45.46,42.63 | C3.1 32.13,39.08 | R9.1 32.05,39.15 32.13,39.08 | U1.58 49.26,41.65 48.28,42.63
XTLGND1  (via drill 0.3)
  Top 0.254: C2.2 52.49,10.45 52.7,10.25 | 52.7,10.25 Q1.GND@0 | C1.2 52.9,10.45 52.7,10.25
  Top 0.305: v54.85,8.35 54.85,10.45 C1.2
  Bottom 0.406: 56.71,16.81 56.71,21.13
  pour Bottom: 48.13,8.09 48.13,16.73 48.43,16.73 49,17.29 56.76,17.23 57.27,16.73 57.27,8.09 56.76,7.58 48.64,7.58
XTLGND2  (via drill 0.8)
  Top 0.406: C3.2 29.08,39.08 v28.32,38.32 29.33,37.3 C4.2
  Bottom 0.406: 39.49,42.63 40.94,42.63
  pour Bottom: 33.4,34.51 27.3,34.51 26.79,35.01 26.79,43.14 27.3,43.65 39.49,43.65 40,43.14 40,35.27 39.49,34.76 37.97,34.76 37.46,35.27 37.46,42.38 36.95,42.89 34.41,42.89 33.9,42.38 33.9,35.01

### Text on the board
tNames: 5V LDOI | GND | GND | Rev.: 1.1 RoHS | int | Vcc | ext | 1 | SBW -> | JTAG -> | MSP-TS430RGC64B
